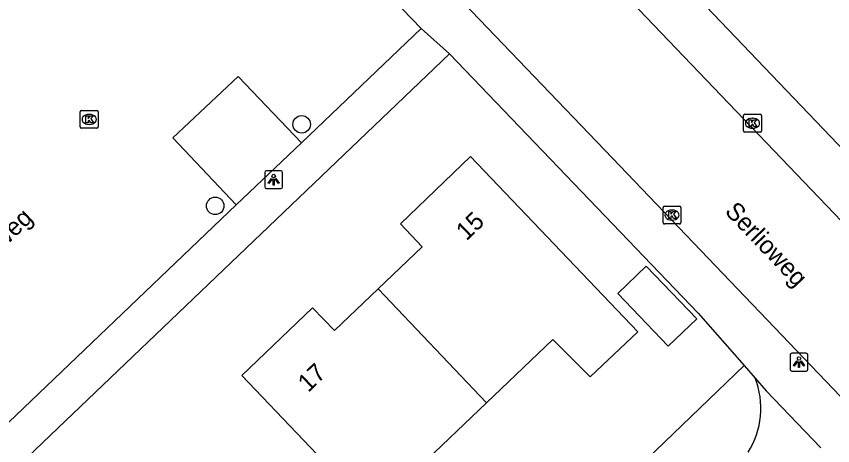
# Model space of a CAD drawing. Extents: x 159353 to 160616, y 385893 to 387321.
# Drawn here: x 159931.48 to 159977.22, y 386403.38 to 386427.42 of the extents above; entities that cross this region are included whole.
import ezdxf

# ---------------------------------------------------------------- set-up
doc = ezdxf.new("R2010")
doc.units = 0
for name, color, linetype in [('IMGEO_Boom', 7, 'Continuous'), ('IMGEO_Groenvoorziening', 7, 'Continuous'), ('IMGEO_Kolk', 7, 'Continuous'), ('IMGEO_Lichtpunt', 7, 'Continuous'), ('IMGEO_Openbare_ruimte_label', 7, 'Continuous'), ('IMGEO_Pand', 7, 'Continuous'), ('IMGEO_Pand_nummerreeks', 7, 'Continuous'), ('IMGEO_Rijbaan_lokaal_open', 7, 'Continuous'), ('IMGEO_Voetpad_halfverhard', 7, 'Continuous'), ('IMGEO_Voetpad_open', 7, 'Continuous')]:
    doc.layers.add(name, color=color, linetype=linetype)

msp = doc.modelspace()

# ---------------------------------------------------------------- linework, layer by layer
at = {"layer": 'IMGEO_Boom'}
for centre in [(159947.469, 386421.371), (159942.624, 386416.807)]:
    msp.add_circle(centre, 0.489, dxfattribs=at)
at = {"layer": 'IMGEO_Groenvoorziening'}
msp.add_lwpolyline([(159972.256, 386407.862), (159964.815, 386400.701)], dxfattribs=at)
at = {"layer": 'IMGEO_Kolk'}
for p, q in [((159935.065, 386421.226), (159935.065, 386422.078)), ((159935.14, 386422.152), (159935.992, 386422.152)), ((159936.066, 386422.078), (159936.066, 386421.226)), ((159935.553, 386421.932), (159935.578, 386421.932)), ((159972.223, 386421.008), (159972.223, 386421.86)), ((159972.298, 386421.934), (159973.15, 386421.934)), ((159972.711, 386421.714), (159972.736, 386421.714)), ((159973.224, 386421.86), (159973.224, 386421.008)), ((159935.992, 386421.152), (159935.14, 386421.152)), ((159935.576, 386421.372), (159935.551, 386421.372)), ((159972.734, 386421.154), (159972.709, 386421.154)), ((159973.15, 386420.934), (159972.298, 386420.934)), ((159967.713, 386415.867), (159967.713, 386416.719)), ((159967.788, 386416.793), (159968.64, 386416.793)), ((159968.201, 386416.573), (159968.226, 386416.573)), ((159968.714, 386416.719), (159968.714, 386415.867)), ((159968.224, 386416.013), (159968.199, 386416.013)), ((159968.64, 386415.793), (159967.788, 386415.793))]:
    msp.add_line(p, q, dxfattribs=at)
for points in [[(159935.065, 386421.226), (159935.065, 386422.078)], [(159935.14, 386422.152), (159935.992, 386422.152)], [(159936.066, 386422.078), (159936.066, 386421.226)], [(159935.386, 386421.852), (159935.509, 386421.852), (159935.509, 386421.701), (159935.639, 386421.852), (159935.803, 386421.852), (159935.657, 386421.701), (159935.81, 386421.452), (159935.658, 386421.452), (159935.573, 386421.616), (159935.509, 386421.549), (159935.509, 386421.452), (159935.386, 386421.452), (159935.386, 386421.852)], [(159972.223, 386421.008), (159972.223, 386421.86)], [(159972.298, 386421.934), (159973.15, 386421.934)], [(159972.544, 386421.634), (159972.667, 386421.634), (159972.667, 386421.483), (159972.797, 386421.634), (159972.961, 386421.634), (159972.815, 386421.483), (159972.968, 386421.234), (159972.816, 386421.234), (159972.731, 386421.398), (159972.667, 386421.331), (159972.667, 386421.234), (159972.544, 386421.234), (159972.544, 386421.634)], [(159973.224, 386421.86), (159973.224, 386421.008)], [(159935.992, 386421.152), (159935.14, 386421.152)], [(159973.15, 386420.934), (159972.298, 386420.934)], [(159967.713, 386415.867), (159967.713, 386416.719)], [(159967.788, 386416.793), (159968.64, 386416.793)], [(159968.034, 386416.493), (159968.157, 386416.493), (159968.157, 386416.342), (159968.287, 386416.493), (159968.451, 386416.493), (159968.305, 386416.342), (159968.458, 386416.093), (159968.306, 386416.093), (159968.221, 386416.257), (159968.157, 386416.19), (159968.157, 386416.093), (159968.034, 386416.093), (159968.034, 386416.493)], [(159968.714, 386416.719), (159968.714, 386415.867)], [(159968.64, 386415.793), (159967.788, 386415.793)]]:
    msp.add_lwpolyline(points, dxfattribs=at)
for centre, start, end in [((159935.142, 386422.076), 91.552, 178.448), ((159935.142, 386422.076), 91.552, 178.448), ((159935.99, 386422.076), 1.552, 88.448), ((159935.99, 386422.076), 1.552, 88.448), ((159972.3, 386421.858), 91.552, 178.448), ((159972.3, 386421.858), 91.552, 178.448), ((159973.148, 386421.858), 1.552, 88.448), ((159973.148, 386421.858), 1.552, 88.448), ((159935.142, 386421.228), 181.552, 268.448), ((159935.142, 386421.228), 181.552, 268.448), ((159935.99, 386421.228), 271.552, 358.448), ((159935.99, 386421.228), 271.552, 358.448), ((159972.3, 386421.01), 181.552, 268.448), ((159972.3, 386421.01), 181.552, 268.448), ((159973.148, 386421.01), 271.552, 358.448), ((159973.148, 386421.01), 271.552, 358.448), ((159967.79, 386416.717), 91.552, 178.448), ((159967.79, 386416.717), 91.552, 178.448), ((159968.638, 386416.717), 1.552, 88.448), ((159968.638, 386416.717), 1.552, 88.448), ((159967.79, 386415.869), 181.552, 268.448), ((159967.79, 386415.869), 181.552, 268.448), ((159968.638, 386415.869), 271.552, 358.448), ((159968.638, 386415.869), 271.552, 358.448)]:
    msp.add_arc(centre, 0.0765, start, end, dxfattribs=at)
for centre, major_axis, ratio, start_param, end_param in [((159935.552, 386421.652), (-0.387, 0.002), 0.722429, 4.712389, 7.853982), ((159935.577, 386421.652), (-0.39, 0.002), 0.717154, 1.570796, 4.712389), ((159972.71, 386421.434), (-0.387, 0.002), 0.722429, 4.712389, 7.853982), ((159972.735, 386421.434), (-0.39, 0.002), 0.717154, 1.570796, 4.712389), ((159968.2, 386416.293), (-0.387, 0.002), 0.722429, 4.712389, 7.853982), ((159968.225, 386416.293), (-0.39, 0.002), 0.717154, 1.570796, 4.712389)]:
    msp.add_ellipse(centre, major_axis=major_axis, ratio=ratio, start_param=start_param, end_param=end_param, dxfattribs=at)
at = {"layer": 'IMGEO_Lichtpunt'}
for p, q in [((159946.305, 386418.775), (159945.497, 386418.775)), ((159946.305, 386418.775), (159945.497, 386418.775)), ((159945.403, 386418.68), (159945.403, 386417.873)), ((159945.403, 386418.68), (159945.403, 386417.873)), ((159946.399, 386417.873), (159946.399, 386418.68)), ((159946.399, 386417.873), (159946.399, 386418.68)), ((159945.497, 386417.779), (159946.305, 386417.779)), ((159945.497, 386417.779), (159946.305, 386417.779)), ((159974.829, 386408.46), (159974.829, 386407.653)), ((159974.829, 386408.46), (159974.829, 386407.653)), ((159975.731, 386408.555), (159974.923, 386408.555)), ((159975.731, 386408.555), (159974.923, 386408.555)), ((159975.825, 386407.653), (159975.825, 386408.46)), ((159975.825, 386407.653), (159975.825, 386408.46)), ((159974.923, 386407.559), (159975.731, 386407.559)), ((159974.923, 386407.559), (159975.731, 386407.559))]:
    msp.add_line(p, q, dxfattribs=at)
for points in [[(159945.777, 386418.344), (159945.816, 386418.316), (159945.628, 386418.054), (159945.59, 386418.081), (159945.777, 386418.344)], [(159945.989, 386418.316), (159946.027, 386418.343), (159946.214, 386418.081), (159946.175, 386418.053), (159945.989, 386418.316)], [(159945.879, 386418.296), (159945.926, 386418.296), (159945.926, 386417.974), (159945.879, 386417.974), (159945.879, 386418.296)], [(159975.203, 386408.124), (159975.242, 386408.096), (159975.054, 386407.834), (159975.016, 386407.861), (159975.203, 386408.124)], [(159975.305, 386408.076), (159975.352, 386408.076), (159975.352, 386407.754), (159975.305, 386407.754), (159975.305, 386408.076)], [(159975.415, 386408.096), (159975.453, 386408.123), (159975.64, 386407.861), (159975.601, 386407.833), (159975.415, 386408.096)]]:
    msp.add_lwpolyline(points, dxfattribs=at)
for centre in [(159945.902, 386418.478), (159975.328, 386408.258)]:
    msp.add_circle(centre, 0.0994, dxfattribs=at)
for centre, start, end in [((159945.497, 386418.68), 90, 180), ((159945.497, 386418.68), 90, 180), ((159946.305, 386418.68), 0, 90), ((159946.305, 386418.68), 0, 90), ((159945.497, 386417.873), 180, 270), ((159945.497, 386417.873), 180, 270), ((159946.305, 386417.873), 270, 0), ((159946.305, 386417.873), 270, 360), ((159974.923, 386408.46), 90, 180), ((159974.923, 386408.46), 90, 180), ((159975.731, 386408.46), 0, 90), ((159975.731, 386408.46), 0, 90), ((159974.923, 386407.653), 180, 270), ((159974.923, 386407.653), 180, 270), ((159975.731, 386407.653), 270, 0), ((159975.731, 386407.653), 270, 360)]:
    msp.add_arc(centre, 0.0946, start, end, dxfattribs=at)
at = {"layer": 'IMGEO_Pand'}
for points in [[(159951.752, 386412.155), (159954.22, 386414.507), (159953.001, 386415.811), (159956.924, 386419.575), (159966.292, 386409.758), (159963.633, 386407.227), (159961.539, 386409.332), (159957.824, 386405.785)], [(159968.003, 386408.946), (159965.173, 386411.898), (159966.766, 386413.426), (159969.597, 386410.475), (159968.003, 386408.946)], [(159957.824, 386405.785), (159954.061, 386402.191), (159956.141, 386400.024), (159953.477, 386397.488), (159947.571, 386403.692), (159944.124, 386407.313), (159948.08, 386411.099), (159949.314, 386409.832), (159951.752, 386412.155)], [(159951.752, 386412.155), (159957.824, 386405.785)]]:
    msp.add_lwpolyline(points, dxfattribs=at)
at = {"layer": 'IMGEO_Rijbaan_lokaal_open'}
for points in [[(159994.081, 386398.847), (159978.987, 386414.631), (159966.776, 386427.371), (159959.001, 386435.485)], [(159989.116, 386394.139), (159985.901, 386397.504), (159964.882, 386419.488), (159955.677, 386429.094), (159954.005, 386430.807), (159953.939, 386430.875)], [(159952.067, 386428.919), (159954.155, 386426.745)], [(159954.155, 386426.745), (159947.454, 386420.346)], [(159943.804, 386416.861), (159940.244, 386420.61), (159943.907, 386424.049), (159947.454, 386420.346)], [(159943.804, 386416.861), (159929.757, 386403.467)]]:
    msp.add_lwpolyline(points, dxfattribs=at)
at = {"layer": 'IMGEO_Voetpad_halfverhard'}
msp.add_arc((159968.641, 386405.466), 4.554, 327.3512, 21.932, dxfattribs=at)
at = {"layer": 'IMGEO_Voetpad_open'}
for points in [[(159960.298, 386438.251), (160000, 386396.738), (160022.672, 386373.032)], [(159954.155, 386426.745), (159955.745, 386425.325)], [(159955.745, 386425.325), (159921.538, 386392.661)], [(159955.745, 386425.325), (159969.677, 386410.799), (159972.256, 386407.862)], [(159947.454, 386420.346), (159943.804, 386416.861)], [(159972.256, 386407.862), (159972.866, 386407.167)], [(159972.866, 386407.167), (159973.494, 386406.452), (159976.557, 386403.258)]]:
    msp.add_lwpolyline(points, dxfattribs=at)

# ---------------------------------------------------------------- texts
at = {"layer": 'IMGEO_Openbare_ruimte_label'}
for rotation, p in [(313.6226, (159971.124, 386416.451)), (43.6226, (159928.221, 386411.992))]:
    msp.add_text('Serlioweg', height=1, rotation=rotation, dxfattribs=at).set_placement(p)
at = {"layer": 'IMGEO_Pand_nummerreeks'}
for s, rotation, p in [('15', 43.815, (159956.702, 386414.817)), ('17', 43.7421, (159947.839, 386406.328))]:
    msp.add_text(s, height=1, rotation=rotation, dxfattribs=at).set_placement(p)

doc.saveas('drawing.dxf')
